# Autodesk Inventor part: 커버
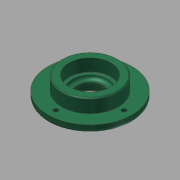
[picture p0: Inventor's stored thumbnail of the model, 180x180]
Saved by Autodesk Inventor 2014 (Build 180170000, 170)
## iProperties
Company: 한국ATC센터
Created: 2014-10
Part Number: 커버
Document SubType Name: Modeling
Designer: KYOUNG IL JANG
Density: 7.86 g/cm^3
Mass: 351.567 g
Surface Area: 161.165 cm^2
Volume: 44.7286 cm^3
Material: 강철, 연강
Appearance: 강철
Author: KYOUNG IL JANG
Revision Number: 1
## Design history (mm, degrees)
sketch "스케치1"
  geometry: C1 r 40 at (0, 0); 1 further point
  constraints: 1 centre point, 1 coincident
  dimensions: "d0" = 80 diameter of C1
extrude "돌출1" new body sketch "스케치1" distance "d1" = 7; taper "d2" = 0 deg
sketch "스케치2"
  geometry: C1 r 27 at (0, 0); 1 further point
  constraints: 1 centre point, 1 coincident
  dimensions: "d3" = 54 diameter of C1
extrude "돌출2" join sketch "스케치2" distance "d4" = 13; taper "d5" = 0 deg
sketch "스케치3"
  geometry: C1 r 20 at (0, 0); 1 further point
  constraints: 1 centre point, 1 coincident
  dimensions: "d6" = 40 diameter of C1
extrude "돌출3" join sketch "스케치3" distance "d7" = 5; taper "d8" = 0 deg
hole "구멍1" diameter "d11" = 25; stored, may be unused: countersink angle "d15" = 90 deg, drill point angle "d17" = 118 deg; dims "d9" = 10, "d10" = 10, "d12" = 6, "d13" = 32, "d14" = 8.3, "d16" = 8
hole "구멍2" diameter "d20" = 34; stored, may be unused: countersink angle "d24" = 90 deg, drill point angle "d26" = 0 deg; dims "d18" = 10, "d19" = 10, "d21" = 6, "d22" = 40, "d23" = 12, "d25" = 3
fillet "모깎기2" dims "d34" = 3
fillet "모깎기1" dims "d27" = 0.3
chamfer "모따기1" distance "d28" = 1; stored, may be unused: second distance "d29" = 2, angle "d30" = 45 deg
chamfer "모따기2" distance "d31" = 1.2; stored, may be unused: second distance "d32" = 2, angle "d33" = 30 deg
sketch "스케치4" dims "d35" = 65
  geometry: 3 further points
  constraints: 2 horizontal alignment, 1 coincident, 2 other
hole "구멍3" sketch "스케치4" at (32.5, 0) diameter "d36" = 4.5; stored, may be unused: countersink angle "d40" = 90 deg, drill point angle "d42" = 118 deg; dims "d37" = 6, "d38" = 8, "d39" = 4.4, "d41" = 13
node "솔리드1"
pattern_circular "원형 패턴1" dims angle "d44" = 360 deg
